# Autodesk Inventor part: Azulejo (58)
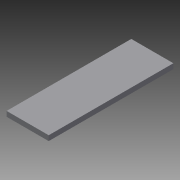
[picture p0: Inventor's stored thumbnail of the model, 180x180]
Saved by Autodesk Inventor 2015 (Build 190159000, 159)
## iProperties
Created: 2015-04
Part Number: Azulejo (58)
Material: Genérico
Document SubType Name: Modeling
Designer: Felipe
Density: 1 g/cm^3
Appearance: Padrão
Author: Felipe
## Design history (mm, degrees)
sketch "Sketch1"
  geometry: L1 (74.31, 25.784)-(574.31, 25.784); L2 (574.31, 25.784)-(574.31, 1505.784); L3 (574.31, 1505.784)-(74.31, 1505.784); L4 (74.31, 1505.784)-(74.31, 25.784); 1 further point
  constraints: 8 end point
extrude "Extrusion1" new body sketch "Sketch1" distance "d0" = 60; taper "d1" = 0 deg
body "Solid1"
